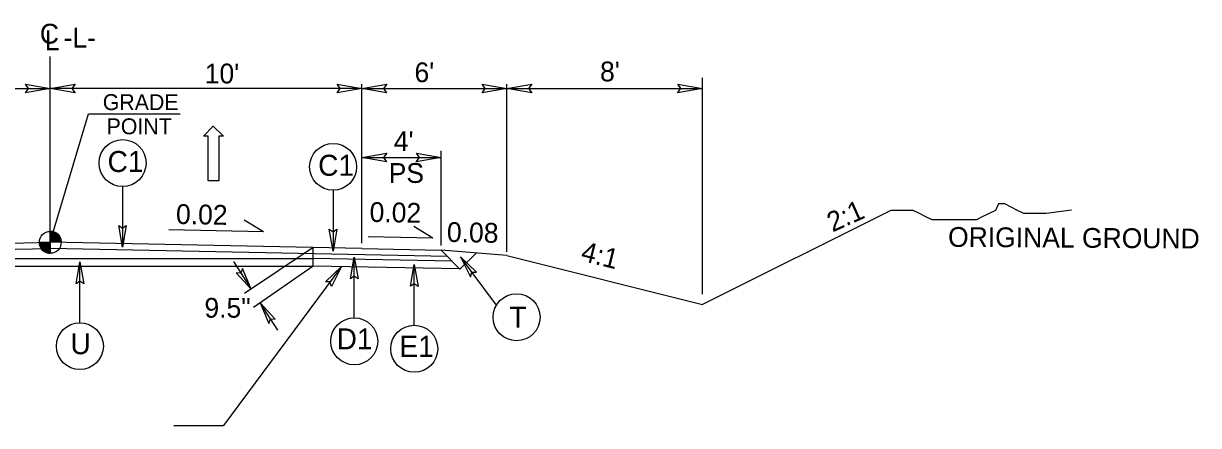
# Model space of a CAD drawing. Extents: x 2111095 to 2115970, y 670428 to 672393.
# Drawn here: x 2112322.8 to 2112378.6, y 670427.8 to 670446.9 of the extents above; entities that cross this region are included whole.
import ezdxf

# ---------------------------------------------------------------- set-up
doc = ezdxf.new("R2010")
doc.units = 0
for name, color, linetype in [('Old_Level_1', 7, 'Continuous'), ('Old_Level_11', 7, 'Continuous'), ('Old_Level_2', 7, 'Continuous'), ('Old_Level_20', 7, 'Continuous'), ('Old_Level_3', 7, 'Continuous'), ('Prop Dimension', 7, 'Continuous'), ('Prop Dimension Text', 7, 'Continuous'), ('Prop Lane Arrow CELL', 7, 'Continuous'), ('Typical ID Circle CELL', 7, 'Continuous'), ('Typical Terminator CELL', 7, 'Continuous'), ('Typical Text ID Circle CELL', 7, 'Continuous')]:
    doc.layers.add(name, color=color, linetype=linetype)

msp = doc.modelspace()

# ---------------------------------------------------------------- linework, layer by layer
at = {"layer": 'Old_Level_1'}
for p, q in [((2112324.117, 670436.535), (2112324.118, 670445.355)), ((2112363.966, 670438.052), (2112355.032, 670433.586)), ((2112324.117, 670436.535), (2112324.117, 670437.054)), ((2112309.343, 670436.241), (2112324.117, 670436.535)), ((2112323.599, 670436.535), (2112324.117, 670436.535)), ((2112324.116, 670436.017), (2112324.117, 670436.535)), ((2112324.117, 670436.535), (2112324.116, 670436.017)), ((2112338.892, 670436.238), (2112324.117, 670436.535)), ((2112324.636, 670436.535), (2112324.117, 670436.535)), ((2112305.29, 670435.864), (2112324.117, 670436.238)), ((2112342.945, 670435.86), (2112324.117, 670436.238)), ((2112336.575, 670435.41), (2112336.575, 670436.285)), ((2112338.892, 670436.238), (2112342.642, 670436.163)), ((2112345.766, 670435.903), (2112342.642, 670436.163)), ((2112342.642, 670436.163), (2112343.54, 670435.265)), ((2112343.54, 670435.265), (2112344.3, 670436.025)), ((2112345.766, 670435.903), (2112355.032, 670433.586)), ((2112311.542, 670435.768), (2112324.117, 670435.768)), ((2112311.542, 670435.41), (2112324.117, 670435.41)), ((2112324.117, 670435.768), (2112336.575, 670435.768)), ((2112324.117, 670435.41), (2112336.575, 670435.41)), ((2112343.169, 670435.636), (2112336.575, 670435.768)), ((2112343.535, 670435.27), (2112336.575, 670435.41))]:
    msp.add_line(p, q, dxfattribs=at)
for points in [[(2112372.529, 670438.053), (2112371.328, 670437.903), (2112371.027, 670437.903), (2112370.576, 670437.903), (2112370.276, 670437.903), (2112369.975, 670438.052), (2112369.675, 670438.203), (2112369.374, 670438.354), (2112369.074, 670438.354), (2112368.923, 670438.052), (2112368.623, 670437.903), (2112368.322, 670437.752), (2112368.022, 670437.602), (2112367.722, 670437.602), (2112367.421, 670437.602), (2112367.121, 670437.602), (2112366.82, 670437.602), (2112366.52, 670437.602), (2112366.219, 670437.602), (2112365.919, 670437.602), (2112365.619, 670437.751), (2112365.318, 670437.902), (2112365.018, 670438.052), (2112364.567, 670438.052), (2112364.266, 670438.052), (2112363.966, 670438.052)], [(2112324.122, 670437.054), (2112324.122, 670437.054), (2112324.122, 670436.535)], [(2112324.132, 670437.054), (2112324.132, 670436.535)], [(2112324.143, 670437.053), (2112324.143, 670436.535)], [(2112324.153, 670437.053), (2112324.153, 670436.535)], [(2112324.163, 670437.051), (2112324.163, 670436.535)], [(2112324.174, 670437.05), (2112324.174, 670436.535)], [(2112324.184, 670437.049), (2112324.184, 670436.535)], [(2112324.195, 670437.048), (2112324.195, 670436.535)], [(2112324.205, 670437.047), (2112324.205, 670436.535)], [(2112324.215, 670437.045), (2112324.215, 670436.535)], [(2112324.226, 670437.042), (2112324.226, 670436.535)], [(2112324.236, 670437.04), (2112324.236, 670436.535)], [(2112324.246, 670437.038), (2112324.246, 670436.535)], [(2112324.257, 670437.034), (2112324.257, 670436.535)], [(2112324.267, 670437.032), (2112324.267, 670436.535)], [(2112324.278, 670437.028), (2112324.277, 670436.535)], [(2112324.288, 670437.025), (2112324.288, 670436.535)], [(2112324.298, 670437.021), (2112324.298, 670436.535)], [(2112324.309, 670437.017), (2112324.309, 670436.535)], [(2112324.319, 670437.012), (2112324.319, 670436.535)], [(2112324.329, 670437.008), (2112324.329, 670436.535)], [(2112324.34, 670437.003), (2112324.34, 670436.535)], [(2112324.35, 670436.998), (2112324.35, 670436.535)], [(2112324.36, 670436.993), (2112324.36, 670436.535)], [(2112324.371, 670436.987), (2112324.371, 670436.535)], [(2112324.381, 670436.981), (2112324.381, 670436.535)], [(2112324.392, 670436.975), (2112324.392, 670436.535)], [(2112324.402, 670436.968), (2112324.402, 670436.535)], [(2112324.412, 670436.962), (2112324.412, 670436.535)], [(2112324.423, 670436.953), (2112324.423, 670436.535)], [(2112324.433, 670436.947), (2112324.433, 670436.535)], [(2112324.443, 670436.938), (2112324.443, 670436.535)], [(2112324.454, 670436.929), (2112324.454, 670436.535)], [(2112323.601, 670436.535), (2112323.601, 670436.479)], [(2112323.612, 670436.535), (2112323.611, 670436.418)], [(2112323.622, 670436.535), (2112323.622, 670436.381)], [(2112323.632, 670436.535), (2112323.632, 670436.35)], [(2112323.643, 670436.535), (2112323.643, 670436.326)], [(2112323.653, 670436.535), (2112323.653, 670436.304)], [(2112323.663, 670436.535), (2112323.663, 670436.284)], [(2112323.674, 670436.535), (2112323.674, 670436.266)], [(2112323.684, 670436.535), (2112323.684, 670436.25)], [(2112323.695, 670436.535), (2112323.695, 670436.235)], [(2112323.705, 670436.535), (2112323.705, 670436.221)], [(2112323.715, 670436.535), (2112323.715, 670436.208)], [(2112323.726, 670436.535), (2112323.726, 670436.195)], [(2112323.736, 670436.535), (2112323.736, 670436.184)], [(2112323.746, 670436.535), (2112323.746, 670436.172)], [(2112323.757, 670436.535), (2112323.757, 670436.162)], [(2112323.767, 670436.535), (2112323.767, 670436.153)], [(2112323.777, 670436.535), (2112323.777, 670436.144)], [(2112323.788, 670436.535), (2112323.788, 670436.134)], [(2112323.798, 670436.535), (2112323.798, 670436.126)], [(2112323.809, 670436.535), (2112323.809, 670436.118)], [(2112323.819, 670436.535), (2112323.819, 670436.111)], [(2112323.829, 670436.535), (2112323.829, 670436.104)], [(2112323.84, 670436.535), (2112323.84, 670436.097)], [(2112323.85, 670436.535), (2112323.85, 670436.091)], [(2112323.86, 670436.535), (2112323.86, 670436.085)], [(2112323.871, 670436.535), (2112323.871, 670436.079)], [(2112323.881, 670436.535), (2112323.881, 670436.073)], [(2112323.892, 670436.535), (2112323.891, 670436.069)], [(2112323.902, 670436.535), (2112323.902, 670436.064)], [(2112323.912, 670436.535), (2112323.912, 670436.059)], [(2112323.923, 670436.535), (2112323.923, 670436.055)], [(2112323.933, 670436.535), (2112323.933, 670436.05)], [(2112323.943, 670436.535), (2112323.943, 670436.047)], [(2112323.954, 670436.535), (2112323.954, 670436.043)], [(2112323.964, 670436.535), (2112323.964, 670436.04)], [(2112323.974, 670436.535), (2112323.974, 670436.038)], [(2112323.985, 670436.535), (2112323.985, 670436.034)], [(2112323.995, 670436.535), (2112323.995, 670436.032)], [(2112324.006, 670436.535), (2112324.006, 670436.029)], [(2112324.016, 670436.535), (2112324.016, 670436.027)], [(2112324.026, 670436.535), (2112324.026, 670436.025)], [(2112324.037, 670436.535), (2112324.037, 670436.024)], [(2112324.047, 670436.535), (2112324.047, 670436.021)], [(2112324.057, 670436.535), (2112324.057, 670436.02)], [(2112324.068, 670436.535), (2112324.068, 670436.019)], [(2112324.078, 670436.535), (2112324.078, 670436.018)], [(2112324.089, 670436.535), (2112324.088, 670436.018)], [(2112324.099, 670436.535), (2112324.099, 670436.017)], [(2112324.109, 670436.535), (2112324.109, 670436.017), (2112324.109, 670436.017)], [(2112324.464, 670436.92), (2112324.464, 670436.535)], [(2112324.475, 670436.911), (2112324.474, 670436.535)], [(2112324.485, 670436.9), (2112324.485, 670436.535)], [(2112324.495, 670436.89), (2112324.495, 670436.535)], [(2112324.506, 670436.879), (2112324.506, 670436.535)], [(2112324.516, 670436.866), (2112324.516, 670436.535)], [(2112324.526, 670436.853), (2112324.526, 670436.535)], [(2112324.537, 670436.839), (2112324.537, 670436.535)], [(2112324.547, 670436.824), (2112324.547, 670436.535)], [(2112324.557, 670436.808), (2112324.557, 670436.535)], [(2112324.568, 670436.791), (2112324.568, 670436.535)], [(2112324.578, 670436.773), (2112324.578, 670436.535)], [(2112324.589, 670436.751), (2112324.589, 670436.535)], [(2112324.599, 670436.726), (2112324.599, 670436.535)], [(2112324.609, 670436.698), (2112324.609, 670436.535)], [(2112324.62, 670436.662), (2112324.62, 670436.535)], [(2112324.63, 670436.609), (2112324.63, 670436.535)]]:
    msp.add_lwpolyline(points, dxfattribs=at)
msp.add_circle((2112324.117, 670436.535), 0.518, dxfattribs=at)
for start, end in [(359.9851, 89.9851), (179.9851, 269.9851)]:
    msp.add_arc((2112324.117, 670436.535), 0.518, start, end, dxfattribs=at)
at = {"layer": 'Old_Level_11'}
for p, q in [((2112355.032, 670434.082), (2112355.033, 670444.34)), ((2112309.344, 670443.832), (2112324.118, 670443.831)), ((2112338.893, 670443.829), (2112324.118, 670443.831)), ((2112338.892, 670436.491), (2112338.893, 670444.039)), ((2112338.892, 670436.826), (2112338.893, 670444.039)), ((2112338.893, 670443.829), (2112345.767, 670443.829)), ((2112345.766, 670436.085), (2112345.767, 670444.037)), ((2112345.767, 670443.829), (2112355.033, 670443.828)), ((2112342.642, 670436.389), (2112342.642, 670440.871)), ((2112338.893, 670440.556), (2112342.643, 670440.556)), ((2112327.542, 670439.18), (2112327.542, 670436.301)), ((2112337.526, 670439.002), (2112337.526, 670436.122)), ((2112338.529, 670432.953), (2112338.529, 670435.836)), ((2112345.265, 670433.549), (2112343.566, 670435.848)), ((2112341.372, 670432.6), (2112341.372, 670435.479))]:
    msp.add_line(p, q, dxfattribs=at)
for points in [[(2112327.72, 670437.333), (2112327.542, 670436.301), (2112327.359, 670437.338), (2112327.542, 670437.207)], [(2112337.704, 670437.154), (2112337.526, 670436.122), (2112337.343, 670437.16), (2112337.526, 670437.028)], [(2112338.351, 670434.805), (2112338.529, 670435.836), (2112338.712, 670434.799), (2112338.529, 670434.931)], [(2112344.322, 670435.124), (2112343.566, 670435.848), (2112344.035, 670434.905), (2112344.104, 670435.12)], [(2112337.159, 670434.662), (2112337.917, 670435.383), (2112337.445, 670434.441), (2112337.376, 670434.657)], [(2112341.194, 670434.448), (2112341.372, 670435.479), (2112341.555, 670434.442), (2112341.372, 670434.574)]]:
    msp.add_lwpolyline(points, close=True, dxfattribs=at)
for centre in [(2112327.542, 670440.294), (2112337.527, 670440.115), (2112346.223, 670432.981), (2112338.529, 670431.839), (2112341.372, 670431.486)]:
    msp.add_circle(centre, 1.114, dxfattribs=at)
at = {"layer": 'Old_Level_2'}
for p, q in [((2112334.218, 670437.03), (2112333.311, 670437.578)), ((2112334.218, 670437.03), (2112329.73, 670437.12)), ((2112342.258, 670436.734), (2112341.351, 670437.282)), ((2112342.258, 670436.734), (2112339.186, 670436.795))]:
    msp.add_line(p, q, dxfattribs=at)
at = {"layer": 'Old_Level_3'}
for p, q in [((2112324.117, 670436.535), (2112325.922, 670442.624)), ((2112325.922, 670442.624), (2112330.281, 670442.623)), ((2112337.917, 670435.383), (2112332.336, 670427.847)), ((2112329.978, 670427.847), (2112332.336, 670427.847))]:
    msp.add_line(p, q, dxfattribs=at)
at = {"layer": 'Prop Dimension'}
for p, q in [((2112336.575, 670436.285), (2112333.327, 670434.108)), ((2112332.799, 670435.618), (2112333.638, 670434.316)), ((2112336.575, 670435.41), (2112333.756, 670433.449)), ((2112334.903, 670432.362), (2112334.063, 670433.663))]:
    msp.add_line(p, q, dxfattribs=at)
at = {"layer": 'Prop Lane Arrow CELL'}
for p, q in [((2112331.375, 670441.572), (2112331.846, 670442.05)), ((2112331.846, 670442.05), (2112332.332, 670441.572)), ((2112331.603, 670441.572), (2112331.375, 670441.572)), ((2112331.603, 670439.446), (2112331.603, 670441.572)), ((2112332.332, 670441.572), (2112332.104, 670441.572)), ((2112332.104, 670441.572), (2112332.104, 670439.446)), ((2112332.104, 670439.446), (2112331.603, 670439.446))]:
    msp.add_line(p, q, dxfattribs=at)
at = {"layer": 'Typical ID Circle CELL'}
msp.add_line((2112325.518, 670432.723), (2112325.518, 670435.602), dxfattribs=at)
msp.add_circle((2112325.518, 670431.61), 1.114, dxfattribs=at)
at = {"layer": 'Typical Terminator CELL'}
for points in [[(2112322.946, 670444.033), (2112324.118, 670443.831), (2112322.94, 670443.623), (2112323.09, 670443.831)], [(2112325.29, 670443.629), (2112324.118, 670443.831), (2112325.296, 670444.039), (2112325.146, 670443.831)], [(2112337.721, 670444.031), (2112338.893, 670443.829), (2112337.714, 670443.621), (2112337.864, 670443.829)], [(2112340.064, 670443.627), (2112338.893, 670443.829), (2112340.071, 670444.038), (2112339.921, 670443.829)], [(2112344.595, 670444.031), (2112345.767, 670443.829), (2112344.589, 670443.621), (2112344.739, 670443.829)], [(2112346.939, 670443.627), (2112345.767, 670443.829), (2112346.945, 670444.037), (2112346.796, 670443.829)], [(2112353.861, 670444.03), (2112355.033, 670443.828), (2112353.854, 670443.62), (2112354.004, 670443.828)], [(2112340.064, 670440.354), (2112338.893, 670440.556), (2112340.071, 670440.764), (2112339.921, 670440.556)], [(2112341.471, 670440.758), (2112342.643, 670440.556), (2112341.464, 670440.347), (2112341.614, 670440.556)], [(2112325.34, 670434.571), (2112325.518, 670435.602), (2112325.701, 670434.565), (2112325.518, 670434.697)], [(2112332.93, 670435.087), (2112333.638, 670434.316), (2112333.23, 670435.287), (2112333.148, 670435.077)], [(2112334.772, 670432.893), (2112334.063, 670433.663), (2112334.472, 670432.692), (2112334.554, 670432.903)]]:
    msp.add_lwpolyline(points, close=True, dxfattribs=at)

# ---------------------------------------------------------------- texts
at = {"layer": 'Old_Level_1'}
for s, height, rotation, p in [('2:1', 0.9391, 24.2085, (2112361.206, 670437.002)), ('ORIGINAL GROUND', 0.93912, 359.6033, (2112366.677, 670436.322)), ('4:1', 0.9391, 345.9584, (2112349.222, 670435.679))]:
    msp.add_text(s, height=height, rotation=rotation, dxfattribs=at).set_placement(p)
at = {"layer": 'Old_Level_11'}
for s, height, rotation, p in [('C', 0.939, 359.9946, (2112323.621, 670445.96)), ('L', 0.939, 359.9415, (2112323.855, 670445.644)), ('-L-', 0.9391, 359.9946, (2112324.747, 670445.773)), ("10'", 0.9391, 359.9946, (2112331.439, 670444.071)), ("6'", 0.9391, 359.9946, (2112341.383, 670444.129)), ("8'", 0.9391, 359.9946, (2112350.18, 670444.168)), ("4'", 0.9391, 359.9946, (2112340.403, 670440.865)), ('PS', 0.9391, 359.9946, (2112340.159, 670439.353))]:
    msp.add_text(s, height=height, rotation=rotation, dxfattribs=at).set_placement(p)
at = {"layer": 'Old_Level_20'}
for s, height, p in [('C1', 0.9971, (2112326.832, 670439.869)), ('C1', 0.9971, (2112336.816, 670439.69)), ('T', 0.997, (2112345.885, 670432.485)), ('D1', 0.9971, (2112337.69, 670431.457)), ('E1', 0.9971, (2112340.669, 670431.104))]:
    msp.add_text(s, height=height, dxfattribs=at).set_placement(p)
at = {"layer": 'Old_Level_3'}
for s, height, rotation, p in [('GRADE', 0.7558, 359.9946, (2112326.604, 670442.805)), ('POINT', 0.7558, 359.9946, (2112326.786, 670441.659)), ('0.02', 0.9391, 358.8489, (2112330.069, 670437.41)), ('0.02', 0.9391, 358.8596, (2112339.248, 670437.507)), ('0.08', 0.9391, 358.8596, (2112342.913, 670436.557))]:
    msp.add_text(s, height=height, rotation=rotation, dxfattribs=at).set_placement(p)
at = {"layer": 'Prop Dimension Text'}
msp.add_text('9.5"', height=0.9391, rotation=360, dxfattribs=at).set_placement((2112331.425, 670432.961))
at = {"layer": 'Typical Text ID Circle CELL'}
msp.add_text('U', height=0.997, dxfattribs=at).set_placement((2112325.072, 670431.228))

doc.saveas('drawing.dxf')
